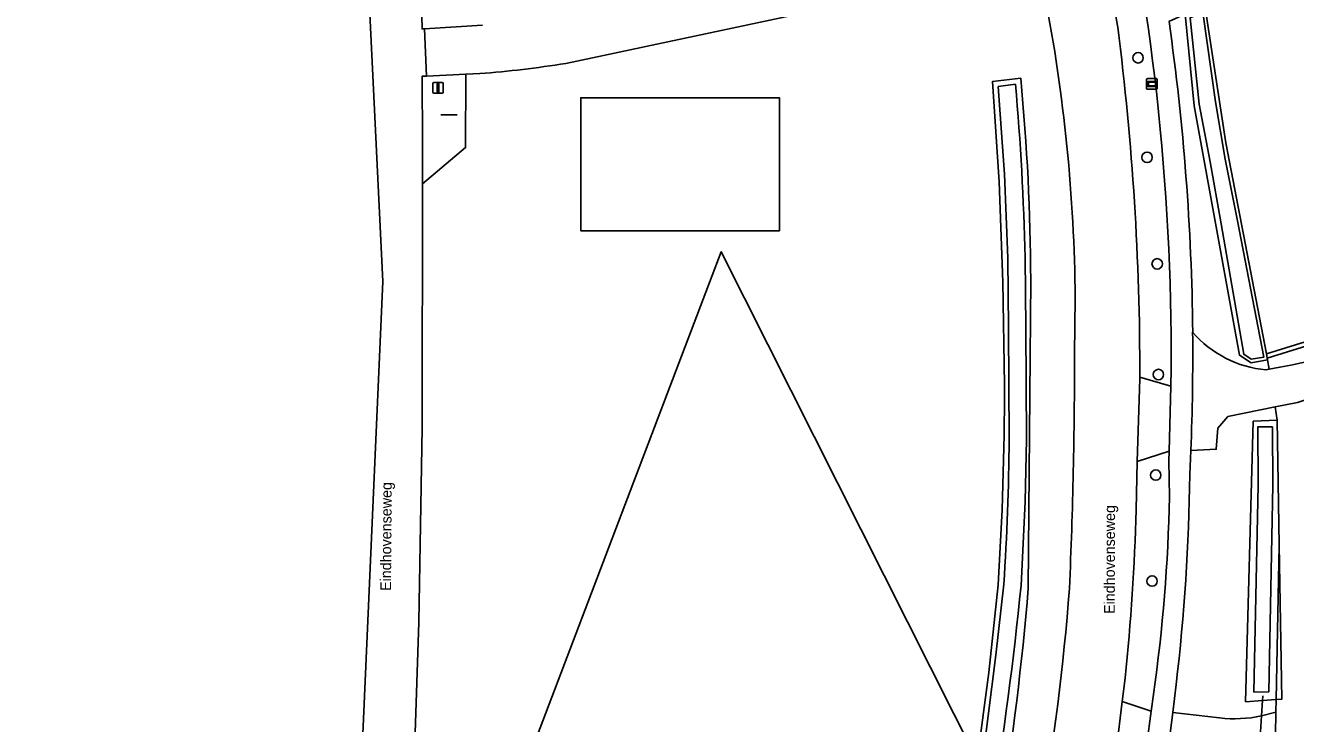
# Model space of a CAD drawing. Extents: x 162510 to 163918, y 388494 to 389774.
# Drawn here: x 162555.5 to 162674.3, y 389562 to 389627.2 of the extents above; entities that cross this region are included whole.
import ezdxf

# ---------------------------------------------------------------- set-up
doc = ezdxf.new("R2010")
doc.units = 0
for name, color, linetype in [('IMGEO_Berm_groen', 7, 'Continuous'), ('IMGEO_Boom', 7, 'Continuous'), ('IMGEO_Duiker', 7, 'Continuous'), ('IMGEO_Erf', 7, 'Continuous'), ('IMGEO_Fietspad_gesloten', 7, 'Continuous'), ('IMGEO_Grasland_overig', 7, 'Continuous'), ('IMGEO_Groenvoorziening', 7, 'Continuous'), ('IMGEO_Haag', 7, 'Continuous'), ('IMGEO_Hek', 7, 'Continuous'), ('IMGEO_Loofbos', 7, 'Continuous'), ('IMGEO_Oever', 7, 'Continuous'), ('IMGEO_Openbare_ruimte_label', 7, 'Continuous'), ('IMGEO_Rijbaan_lokaal_gesloten', 7, 'Continuous'), ('IMGEO_Rijbaan_lokaal_open', 7, 'Continuous'), ('IMGEO_Rijbaan_regionaal_gesloten', 7, 'Continuous'), ('IMGEO_Verkeersbordpaal', 7, 'Continuous'), ('IMGEO_Verklikker', 7, 'Continuous'), ('IMGEO_Waterloop', 7, 'Continuous')]:
    doc.layers.add(name, color=color, linetype=linetype)

msp = doc.modelspace()

# ---------------------------------------------------------------- linework, layer by layer
at = {"layer": 'IMGEO_Berm_groen'}
for points in [[(162645.63, 389632.12), (162606.04, 389623.7)], [(162598.01, 389622.74), (162596.7, 389622.68), (162596.68, 389615.82), (162592.64, 389612.42), (162592.61, 389589.61), (162592.3, 389571.45), (162591.26, 389539.46), (162589.4, 389507.11), (162588.85, 389500), (162587.36, 389481.75), (162584.99, 389456.28), (162583.5, 389442.96), (162581.3, 389425.76), (162579.8, 389412.03), (162577.24, 389393.15), (162573.3, 389367.99), (162566.49, 389328.54), (162555.54, 389271.65)], [(162647.06, 389593.64), (162646.9, 389603.23), (162646.54, 389612.63), (162645.94, 389622.01), (162648.56, 389622.31)], [(162577.41, 389384.02), (162581.11, 389399), (162582.08, 389406.23), (162584.14, 389417.99), (162585.24, 389425.59), (162589.21, 389455.96), (162590.76, 389474.27), (162592.59, 389500), (162594.1, 389521.6), (162595.14, 389539.18), (162620.58, 389606.08), (162644.49, 389558.55), (162645.59, 389566.74), (162646.45, 389574.95)], [(162649.5, 389603.47), (162649.26, 389574.61)], [(162653.6, 389596.53), (162653.66, 389601.74)], [(162659.7, 389594.37), (162662.6, 389593.5)], [(162662.46, 389583.17), (162662.4, 389586.52), (162662.44, 389587.44), (162659.43, 389586.46), (162659.36, 389581.96)], [(162658.33, 389566.21), (162658.05, 389564.02), (162660.76, 389563.12), (162660.97, 389564.69)]]:
    msp.add_lwpolyline(points, dxfattribs=at)
msp.add_lwpolyline([(162607.45, 389620.49), (162626.01, 389620.49), (162626.01, 389608.04), (162607.45, 389608.04)], close=True, dxfattribs=at)
for centre, radius, start, end in [((162411.67, 389589.96), 248.74, 8.5848, 13.4892), ((162441.8, 389596.35), 220.82, 359.2613, 12.5921), ((162495.41, 389600.13), 158.26, 0.5805, 10.9035), ((162407.92, 389594.89), 251.77, 359.881, 7.346), ((162591.57, 389711.28), 88.77, 274.1589, 279.3792), ((162441.78, 389602.59), 207.72, 0.2412, 5.4466), ((162147.36, 389596.48), 506.23, 357.5204, 0.0055), ((162355.99, 389593.66), 291.06, 356.3143, 359.9944), ((162510.28, 389586.14), 152.21, 351.9014, 358.8829), ((162435.85, 389588.67), 223.61, 354.2359, 358.2813), ((162382.24, 389596.53), 267.92, 346.248, 355.3073), ((162403.45, 389594.56), 250.47, 345.4722, 355.4263)]:
    msp.add_arc(centre, radius, start, end, dxfattribs=at)
at = {"layer": 'IMGEO_Boom'}
for centre in [(162659.53, 389624.22), (162660.37, 389614.91), (162661.32, 389604.95), (162661.43, 389594.6), (162661.18, 389585.2), (162660.84, 389575.29)]:
    msp.add_circle(centre, 0.489, dxfattribs=at)
at = {"layer": 'IMGEO_Duiker'}
msp.add_lwpolyline([(162670.77, 389557.84), (162670.79, 389558.03), (162670.86, 389559.19), (162671.07, 389562.68), (162671.15, 389564.12), (162671.18, 389564.55)], dxfattribs=at)
at = {"layer": 'IMGEO_Erf'}
for points in [[(162665.43, 389634.67), (162665.5, 389630.94), (162665.78, 389629.1), (162667.72, 389616.27), (162671.53, 389596.53), (162682.77, 389600.02), (162694.88, 389604.33), (162700.74, 389606.57), (162706.58, 389609.52), (162708.45, 389610.47), (162716.7, 389614.9), (162716.89, 389614.55), (162708.64, 389610.11), (162706.76, 389609.16), (162700.9, 389606.2), (162695.02, 389603.96), (162682.9, 389599.64), (162671.61, 389596.13), (162671.64, 389595.96), (162671.78, 389595.09)], [(162705.55, 389603.52), (162699.99, 389600.99), (162689.36, 389596.71), (162682.45, 389594.59), (162674.43, 389591.99), (162672.34, 389591.57), (162672.54, 389590.33), (162672.73, 389578.64), (162672.97, 389564.25), (162672.43, 389564.22), (162672.4, 389563.04), (162672.36, 389560.9), (162672.33, 389559.41), (162672.17, 389551.86), (162669.89, 389530.14), (162669.39, 389520.32), (162669.24, 389518.99), (162673.37, 389519.09)]]:
    msp.add_lwpolyline(points, dxfattribs=at)
msp.add_arc((162657.31, 389675.46), 81.66, 280.2033, 291.7402, dxfattribs=at)
at = {"layer": 'IMGEO_Fietspad_gesloten'}
for points in [[(162662.6, 389593.5), (162662.44, 389587.44), (162662.4, 389586.52), (162662.46, 389583.17)], [(162664.36, 389585.24), (162664.46, 389587.51)], [(162647.23, 389500), (162649.65, 389506.83), (162653.09, 389517.43), (162654.04, 389520.66), (162655.77, 389526.57), (162657.82, 389535.12), (162659.45, 389542.7), (162661.68, 389555.43), (162662.38, 389559.85), (162662.78, 389563), (162663.09, 389565.61)], [(162660.97, 389564.69), (162660.76, 389563.12), (162660.35, 389560.06), (162660.02, 389557.64), (162658.49, 389549.48)]]:
    msp.add_lwpolyline(points, dxfattribs=at)
for centre, radius, start, end in [((162441.8, 389596.35), 220.82, 359.2613, 12.5921), ((162443.37, 389596.28), 221.28, 0.5906, 8.1389), ((162443.38, 389596.31), 221.26, 357.7187, 0.5807), ((162480.12, 389587.33), 184.25, 353.2323, 359.3501), ((162510.28, 389586.14), 152.21, 351.9014, 358.8829)]:
    msp.add_arc(centre, radius, start, end, dxfattribs=at)
at = {"layer": 'IMGEO_Grasland_overig'}
msp.add_lwpolyline([(162626.01, 389620.49), (162607.45, 389620.49), (162607.45, 389608.04), (162626.01, 389608.04)], close=True, dxfattribs=at)
at = {"layer": 'IMGEO_Groenvoorziening'}
for points in [[(162605.4, 389628.18), (162606.57, 389628.42), (162606.31, 389629.62), (162605.85, 389631.7), (162604.33, 389638.12), (162595.93, 389637.29), (162596.01, 389635.51), (162596.01, 389628.48), (162595.21, 389628.48), (162595.21, 389635.49), (162595.13, 389637.21), (162592.39, 389636.94), (162592.44, 389634.21), (162592.62, 389626.92), (162592.85, 389626.93), (162598.25, 389627.28)], [(162664.78, 389619.72), (162663.94, 389628.29), (162662.41, 389627.6)], [(162671.49, 389595.03), (162671.63, 389595.06), (162671.78, 389595.09), (162671.64, 389595.96), (162670.09, 389595.68), (162669.02, 389596.4), (162664.78, 389619.72)], [(162671.07, 389562.68), (162672.4, 389563.04), (162672.43, 389564.22), (162671.15, 389564.12), (162669.58, 389564.01), (162670.3, 389590.24), (162672.54, 389590.33), (162672.34, 389591.57), (162667.93, 389590.68), (162666.99, 389589.58), (162666.83, 389587.61), (162664.46, 389587.51), (162664.36, 389585.24)], [(162663.09, 389565.61), (162662.78, 389563), (162667.15, 389562.49)]]:
    msp.add_lwpolyline(points, dxfattribs=at)
for points in [[(162592.64, 389612.42), (162596.68, 389615.82), (162596.7, 389622.68), (162593.02, 389622.5), (162592.63, 389622.51), (162592.65, 389616.27)], [(162716.7, 389614.9), (162708.45, 389610.47), (162706.58, 389609.52), (162700.74, 389606.57), (162694.88, 389604.33), (162682.77, 389600.02), (162671.53, 389596.53), (162671.61, 389596.13), (162682.9, 389599.64), (162695.02, 389603.96), (162700.9, 389606.2), (162706.76, 389609.16), (162708.64, 389610.11), (162716.89, 389614.55)]]:
    msp.add_lwpolyline(points, close=True, dxfattribs=at)
for centre, radius, start, end in [((162443.37, 389596.28), 221.28, 0.5906, 8.1389), ((162672.43, 389605.3), 10.31, 220.8447, 264.7356), ((162480.12, 389587.33), 184.25, 353.2323, 359.3501), ((162668.54, 389574.59), 12.18, 263.413, 281.9618)]:
    msp.add_arc(centre, radius, start, end, dxfattribs=at)
at = {"layer": 'IMGEO_Haag'}
msp.add_lwpolyline([(162716.7, 389614.9), (162708.45, 389610.47), (162706.58, 389609.52), (162700.74, 389606.57), (162694.88, 389604.33), (162682.77, 389600.02), (162671.53, 389596.53), (162671.61, 389596.13), (162682.9, 389599.64), (162695.02, 389603.96), (162700.9, 389606.2), (162706.76, 389609.16), (162708.64, 389610.11), (162716.89, 389614.55)], close=True, dxfattribs=at)
at = {"layer": 'IMGEO_Hek'}
for points in [[(162595.88, 389618.88), (162594.37, 389618.89)], [(162672.73, 389578.64), (162672.43, 389564.22)], [(162672.4, 389563.04), (162672.43, 389564.22)], [(162672.36, 389560.9), (162672.4, 389563.04)]]:
    msp.add_lwpolyline(points, dxfattribs=at)
at = {"layer": 'IMGEO_Loofbos'}
msp.add_lwpolyline([(162644.49, 389558.55), (162620.58, 389606.08), (162595.14, 389539.18), (162594.1, 389521.6), (162592.59, 389500), (162590.76, 389474.27), (162589.21, 389455.96), (162585.24, 389425.59), (162584.14, 389417.99), (162582.08, 389406.23), (162581.11, 389399), (162577.41, 389384.02), (162585.92, 389402.74), (162583.45, 389403.54)], dxfattribs=at)
at = {"layer": 'IMGEO_Oever'}
for points in [[(162665.78, 389629.1), (162664.99, 389628.75), (162663.94, 389628.29), (162664.78, 389619.72), (162669.02, 389596.4), (162670.09, 389595.68), (162671.64, 389595.96), (162671.61, 389596.13), (162671.53, 389596.53), (162667.72, 389616.27)], [(162665.58, 389628.47), (162666.77, 389620.11), (162667.66, 389614.75), (162668.82, 389608.96), (162671.27, 389596.22), (162670.1, 389596.03), (162669.41, 389596.5), (162667.3, 389608.7), (162666.28, 389614.49), (162665.24, 389619.89), (162664.39, 389627.95)], [(162672.54, 389590.33), (162670.3, 389590.24), (162669.58, 389564.01), (162671.15, 389564.12), (162672.43, 389564.22), (162672.97, 389564.25), (162672.73, 389578.64)], [(162671.74, 389564.94), (162670.36, 389564.9), (162670.74, 389584.27), (162670.71, 389589.7), (162672.09, 389589.7), (162672.11, 389584.25)]]:
    msp.add_lwpolyline(points, close=True, dxfattribs=at)
for points in [[(162648.56, 389622.31), (162645.94, 389622.01), (162646.54, 389612.63), (162646.9, 389603.23), (162647.06, 389593.64)], [(162647.48, 389588.56), (162647.43, 389598.95), (162647.36, 389605.49), (162647.06, 389613.33), (162646.47, 389621.53), (162648.07, 389621.74)], [(162648.97, 389605.53), (162649.04, 389598.97), (162649.09, 389588.55), (162648.97, 389582.74), (162648.59, 389574.86)], [(162649.26, 389574.61), (162649.5, 389603.47)], [(162646.45, 389574.95), (162645.59, 389566.74), (162644.49, 389558.55)], [(162645.15, 389559.73), (162646.23, 389568.36), (162646.99, 389574.99)]]:
    msp.add_lwpolyline(points, dxfattribs=at)
for centre, radius, start, end in [((162399.47, 389599.76), 249.57, 1.3254, 5.0527), ((162441.78, 389602.59), 207.72, 0.2412, 5.4466), ((162355.99, 389593.66), 291.06, 356.3143, 359.9944), ((162399.35, 389590.8), 248.14, 356.3473, 359.4839), ((162311.66, 389608.68), 338.63, 347.184, 354.2682), ((162382.24, 389596.53), 267.92, 346.248, 355.3073)]:
    msp.add_arc(centre, radius, start, end, dxfattribs=at)
at = {"layer": 'IMGEO_Rijbaan_lokaal_gesloten'}
for points in [[(162653.66, 389601.74), (162653.6, 389596.53)], [(162659.36, 389581.96), (162659.43, 389586.46), (162659.7, 389594.2), (162659.7, 389594.37)], [(162656.56, 389553.55), (162657.51, 389559.61), (162658.05, 389564.02), (162658.33, 389566.21)]]:
    msp.add_lwpolyline(points, dxfattribs=at)
for centre, radius, start, end in [((162411.67, 389589.96), 248.74, 8.5848, 13.4892), ((162495.41, 389600.13), 158.26, 0.5805, 10.9035), ((162407.92, 389594.89), 251.77, 359.881, 7.346), ((162147.36, 389596.48), 506.23, 357.5204, 0.0055), ((162435.85, 389588.67), 223.61, 354.2359, 358.2813), ((162403.45, 389594.56), 250.47, 345.4722, 355.4263)]:
    msp.add_arc(centre, radius, start, end, dxfattribs=at)
at = {"layer": 'IMGEO_Rijbaan_lokaal_open'}
for points in [[(162606.04, 389623.7), (162645.63, 389632.12)], [(162598.25, 389627.28), (162592.85, 389626.93), (162593.02, 389622.5), (162596.7, 389622.68), (162598.01, 389622.74)], [(162664.46, 389587.51), (162666.83, 389587.61), (162666.99, 389589.58), (162667.93, 389590.68), (162672.34, 389591.57), (162674.43, 389591.99), (162682.45, 389594.59), (162689.36, 389596.71), (162699.99, 389600.99)], [(162671.78, 389595.09), (162671.63, 389595.06), (162671.49, 389595.03)], [(162667.15, 389562.49), (162662.78, 389563), (162662.38, 389559.85), (162668.16, 389559.16), (162670.86, 389559.19), (162672.08, 389559.37), (162672.33, 389559.41), (162672.36, 389560.9), (162672.4, 389563.04)], [(162672.4, 389563.04), (162671.07, 389562.68)]]:
    msp.add_lwpolyline(points, dxfattribs=at)
for points in [[(162662.6, 389593.5), (162659.7, 389594.37), (162659.7, 389594.2), (162659.43, 389586.46), (162662.44, 389587.44)], [(162660.76, 389563.12), (162658.05, 389564.02), (162657.51, 389559.61), (162660.35, 389560.06)]]:
    msp.add_lwpolyline(points, close=True, dxfattribs=at)
for centre, radius, start, end in [((162591.57, 389711.28), 88.77, 274.1589, 279.3792), ((162657.31, 389675.46), 81.66, 280.2033, 291.7402), ((162443.38, 389596.31), 221.26, 357.7187, 0.5807), ((162672.43, 389605.3), 10.31, 220.8447, 264.7356), ((162668.54, 389574.59), 12.18, 263.413, 281.9618)]:
    msp.add_arc(centre, radius, start, end, dxfattribs=at)
at = {"layer": 'IMGEO_Rijbaan_regionaal_gesloten'}
msp.add_lwpolyline([(162591.26, 389539.46), (162592.3, 389571.45), (162592.61, 389589.61), (162592.64, 389612.42), (162592.65, 389616.27), (162592.63, 389622.51), (162593.02, 389622.5), (162592.85, 389626.93), (162592.62, 389626.92), (162592.44, 389634.21), (162592.39, 389636.94), (162592.22, 389646.72), (162591.56, 389666.6), (162589.69, 389703.74), (162588.75, 389716.34), (162585.89, 389750), (162585.28, 389756.02), (162581.37, 389755.95), (162581.76, 389751.6), (162588.95, 389603.29), (162582.93, 389467.23)], dxfattribs=at)
at = {"layer": 'IMGEO_Verkeersbordpaal'}
for p, q in [((162593.61, 389621), (162593.61, 389621.8)), ((162593.61, 389621.8), (162593.61, 389621)), ((162593.71, 389621.9), (162594.5, 389621.9)), ((162594.5, 389621.9), (162593.71, 389621.9)), ((162594.6, 389621.8), (162594.6, 389621)), ((162594.6, 389621), (162594.6, 389621.8)), ((162594.5, 389620.9), (162593.71, 389620.9)), ((162593.71, 389620.9), (162594.5, 389620.9))]:
    msp.add_line(p, q, dxfattribs=at)
msp.add_lwpolyline([(162594.03, 389621.78), (162594.18, 389621.78), (162594.18, 389621.03), (162594.03, 389621.03), (162594.03, 389621.78)], dxfattribs=at)
for centre, start, end in [((162593.71, 389621.8), 90, 180), ((162593.71, 389621.8), 90, 180), ((162594.5, 389621.8), 0, 90), ((162594.5, 389621.8), 360, 90), ((162593.71, 389621), 180, 270), ((162593.71, 389621), 180, 270), ((162594.5, 389621), 270, 0), ((162594.5, 389621), 270, 0)]:
    msp.add_arc(centre, 0.1, start, end, dxfattribs=at)
at = {"layer": 'IMGEO_Verklikker'}
for p, q in [((162660.33, 389621.37), (162660.33, 389622.17)), ((162660.33, 389622.17), (162660.33, 389621.37)), ((162660.43, 389622.27), (162661.21, 389622.27)), ((162661.21, 389622.27), (162660.43, 389622.27)), ((162661.31, 389622.17), (162661.31, 389621.37)), ((162661.31, 389621.37), (162661.31, 389622.17)), ((162661.21, 389621.27), (162660.43, 389621.27)), ((162660.43, 389621.27), (162661.21, 389621.27))]:
    msp.add_line(p, q, dxfattribs=at)
for points in [[(162660.43, 389622), (162661.21, 389622), (162661.21, 389621.54), (162660.43, 389621.54), (162660.43, 389622)], [(162660.49, 389621.94), (162660.49, 389621.6), (162661.15, 389621.6), (162661.15, 389621.94), (162660.49, 389621.94)]]:
    msp.add_lwpolyline(points, dxfattribs=at)
for centre, start, end in [((162660.43, 389622.17), 90, 180), ((162660.43, 389622.17), 90, 180), ((162661.21, 389622.17), 0, 90), ((162661.21, 389622.17), 360, 90), ((162660.43, 389621.37), 180, 270), ((162660.43, 389621.37), 180, 270), ((162661.21, 389621.37), 270, 0), ((162661.21, 389621.37), 270, 0)]:
    msp.add_arc(centre, 0.1, start, end, dxfattribs=at)
at = {"layer": 'IMGEO_Waterloop'}
for points in [[(162665.58, 389628.47), (162664.39, 389627.95), (162665.24, 389619.89), (162666.28, 389614.49), (162667.3, 389608.7), (162669.41, 389596.5), (162670.1, 389596.03), (162671.27, 389596.22), (162668.82, 389608.96), (162667.66, 389614.75), (162666.77, 389620.11)], [(162672.09, 389589.7), (162670.71, 389589.7), (162670.74, 389584.27), (162670.36, 389564.9), (162671.74, 389564.94), (162672.11, 389584.25)]]:
    msp.add_lwpolyline(points, close=True, dxfattribs=at)
for points in [[(162648.07, 389621.74), (162646.47, 389621.53), (162647.06, 389613.33), (162647.36, 389605.49), (162647.43, 389598.95), (162647.48, 389588.56)], [(162648.59, 389574.86), (162648.97, 389582.74), (162649.09, 389588.55), (162649.04, 389598.97), (162648.97, 389605.53)], [(162646.99, 389574.99), (162646.23, 389568.36), (162645.15, 389559.73)]]:
    msp.add_lwpolyline(points, dxfattribs=at)
for centre, radius, start, end in [((162399.47, 389599.76), 249.57, 1.3254, 5.0527), ((162399.35, 389590.8), 248.14, 356.3473, 359.4839), ((162311.66, 389608.68), 338.63, 347.184, 354.2682)]:
    msp.add_arc(centre, radius, start, end, dxfattribs=at)

# ---------------------------------------------------------------- texts
at = {"layer": 'IMGEO_Openbare_ruimte_label'}
for rotation, p in [(89.5989, (162589.71, 389574.36)), (89.8281, (162657.35, 389572.21))]:
    msp.add_text('Eindhovenseweg', height=1, rotation=rotation, dxfattribs=at).set_placement(p)

doc.saveas('drawing.dxf')
